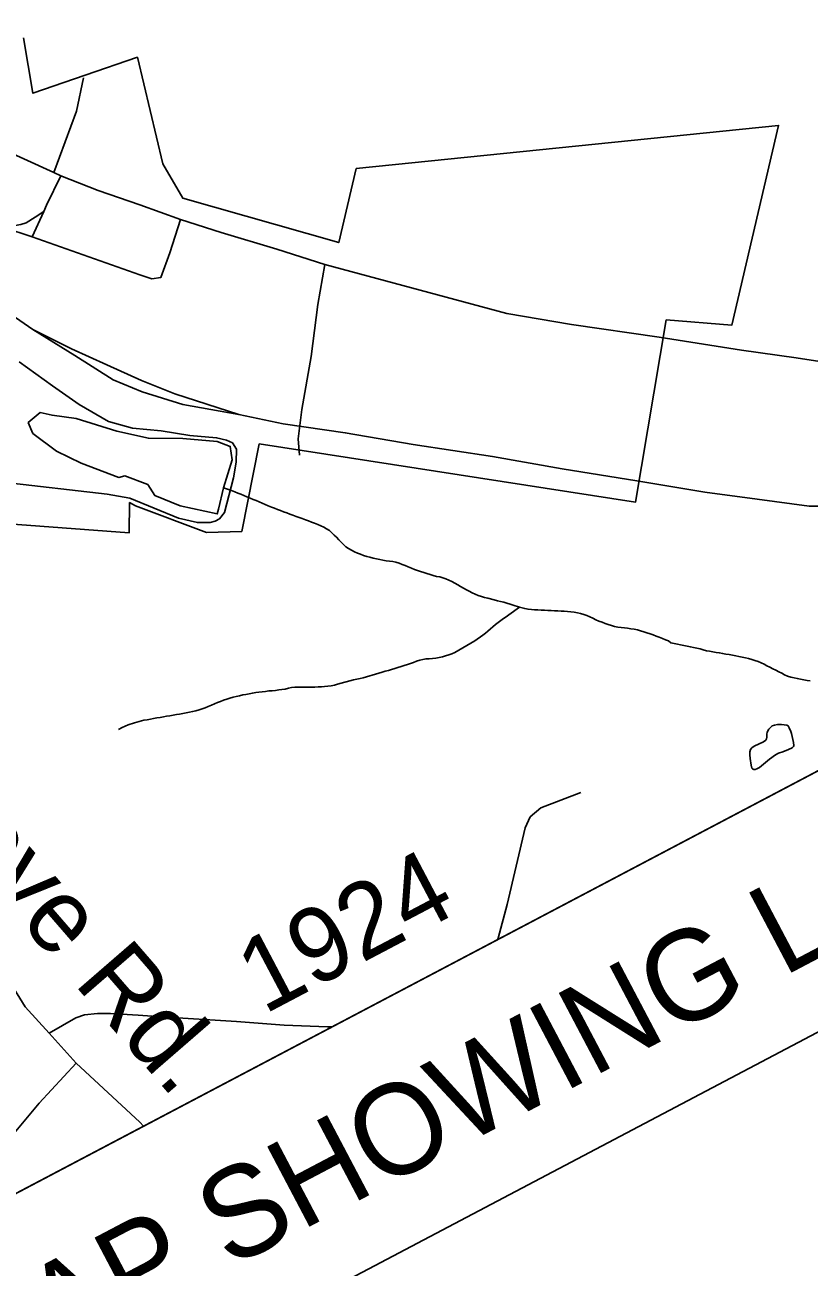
# Model space of a CAD drawing. Extents: x 1379448 to 1382868, y 593769 to 596827.
# Drawn here: x 1379935.9 to 1380091.8, y 595079.7 to 595326.7 of the extents above; entities that cross this region are included whole.
import ezdxf

# ---------------------------------------------------------------- set-up
doc = ezdxf.new("R2010")
doc.units = 0
for name, color, linetype in [('CTL Sheet Text', 7, 'Continuous'), ('Old_Level_1', 7, 'Continuous'), ('Old_Level_11', 7, 'Continuous'), ('Old_Level_29', 7, 'Continuous'), ('Old_Level_32', 7, 'Continuous'), ('Old_Level_35', 7, 'Continuous'), ('Old_Level_44', 7, 'Continuous'), ('Old_Level_48', 7, 'Continuous'), ('Old_Level_49', 7, 'Continuous'), ('Old_Level_62', 7, 'Continuous'), ('Old_Level_8', 7, 'Continuous')]:
    doc.layers.add(name, color=color, linetype=linetype)

msp = doc.modelspace()

# ---------------------------------------------------------------- linework, layer by layer
at = {"layer": 'Old_Level_1'}
msp.add_line((1379782.59, 595014.48), (1380447.79, 595365.17), dxfattribs=at)
msp.add_lwpolyline([(1379782.59, 595014.48), (1380447.79, 595365.17), (1380469.23, 595324.5), (1379804.02, 594973.82)], close=True, dxfattribs=at)
at = {"layer": 'Old_Level_29'}
msp.add_lwpolyline([(1379917.05, 595308.57), (1379941.73, 595297.36), (1379943.11, 595296.68), (1379950.54, 595293.74), (1379958.81, 595290.95), (1379966.9, 595288.02), (1379974.99, 595285.45), (1379986.05, 595282.13), (1379995.58, 595279.03), (1380031.76, 595269.32), (1380044.58, 595267.15), (1380062.05, 595264.62), (1380078.36, 595262.06), (1380089.24, 595260.52), (1380143.01, 595252.19), (1380156.35, 595250.56), (1380166.41, 595248.88), (1380173.7, 595247.81), (1380210.71, 595241.61), (1380212.88, 595241.33)], dxfattribs=at)
at = {"layer": 'Old_Level_32'}
msp.add_line((1379940.77, 595126.25), (1379946.13, 595120.28), dxfattribs=at)
for points in [[(1379834.14, 595274.21), (1379836.12, 595273.42), (1379836.93, 595272.49), (1379837.64, 595271.33), (1379838.6, 595269.4), (1379838.84, 595269.07), (1379841.24, 595264.27), (1379845.01, 595256.93), (1379848.37, 595250.47), (1379852.08, 595243.52), (1379853.91, 595239.94), (1379858.44, 595232.07), (1379873.2, 595210.83), (1379890.84, 595185.94), (1379893.96, 595182.29), (1379900.1, 595176.43), (1379917.01, 595160.6), (1379919.58, 595157.36), (1379926.35, 595146.93), (1379932.52, 595137.16), (1379936.02, 595131.5), (1379940.77, 595126.25)], [(1379997.02, 595127.53), (1379996.12, 595127.5), (1379987.46, 595127.82), (1379977.98, 595128.53), (1379963.11, 595129.47), (1379958.45, 595129.8), (1379952.97, 595130.15), (1379950.35, 595130.17), (1379947.76, 595129.86), (1379946.08, 595129.29), (1379940.77, 595126.25)], [(1379894.35, 595088.2), (1379896.86, 595087.97), (1379904.35, 595089.6), (1379910.09, 595091.85), (1379913.76, 595093.15), (1379917.2, 595094.05), (1379922.27, 595094.82), (1379923.48, 595095.22), (1379924.88, 595095.95), (1379926.29, 595096.87), (1379933.12, 595105.59), (1379938.78, 595112.33), (1379946.13, 595120.28)], [(1379946.13, 595120.28), (1379958.79, 595108.54), (1379959.55, 595107.78)]]:
    msp.add_lwpolyline(points, dxfattribs=at)
at = {"layer": 'Old_Level_35'}
for p, q in [((1379937.42, 595284.53), (1379939.69, 595289.63)), ((1379931.77, 595286.43), (1379937.42, 595284.53))]:
    msp.add_line(p, q, dxfattribs=at)
for points in [[(1379941.73, 595297.36), (1379946.23, 595309.57), (1379947.61, 595316.15)], [(1379939.69, 595289.63), (1379940.24, 595290.87), (1379943.11, 595296.68)], [(1379931.77, 595286.43), (1379935.15, 595287.04), (1379936.17, 595287.37), (1379937.96, 595288.47), (1379939.69, 595289.63)], [(1379937.42, 595284.53), (1379958.82, 595277), (1379961.19, 595276.21), (1379962.94, 595276.46), (1379964.76, 595281.4), (1379966.9, 595288.02)], [(1379990.55, 595241.16), (1379990.27, 595244.42), (1379991.02, 595250.25), (1379992.84, 595260.74), (1379994.19, 595271.08), (1379995.58, 595279.03)], [(1379931.58, 595235.78), (1379952.31, 595233.37), (1379956.82, 595232.58), (1379966.48, 595228.65), (1379970.24, 595227.76), (1379972.75, 595227.76), (1379973.79, 595228.01), (1379974.61, 595228.51), (1379975.6, 595229.73), (1379977.43, 595236.65), (1379977.93, 595239.76), (1379978.01, 595242.34), (1379977.2, 595243.6), (1379976.03, 595244.11), (1379974.06, 595244.62), (1379968.72, 595245.08), (1379963, 595245.97), (1379957.34, 595246.54), (1379952.58, 595247.82), (1379946.75, 595251.26), (1379941.41, 595254.94), (1379934.83, 595259.69)], [(1380029.9, 595144.86), (1380029.99, 595145.1), (1380031.82, 595151.83), (1380035.39, 595167.04), (1380036.35, 595169.23), (1380038.49, 595171.02), (1380046.44, 595174.1)]]:
    msp.add_lwpolyline(points, dxfattribs=at)
at = {"layer": 'Old_Level_44'}
for points in [[(1380192.5, 595230.59), (1380190.44, 595230.58), (1380172.65, 595230.88), (1380154.9, 595230.94), (1380136.64, 595230.75), (1380121.05, 595230.99), (1380104.8, 595231.08), (1380091.84, 595231.04), (1380081.51, 595232.39), (1380071.12, 595233.81), (1380057.56, 595236.06), (1380042.77, 595238.41), (1380028.92, 595240.87), (1380013.14, 595243.25), (1379999.61, 595245.6), (1379987.26, 595247.39), (1379978.45, 595249.24), (1379965.75, 595253.35), (1379959.13, 595256.02), (1379952.22, 595259.1), (1379945.23, 595262.31), (1379937.5, 595266.13), (1379929.48, 595271.61)], [(1380189.94, 595229.24), (1380173.81, 595229.4), (1380151.32, 595229.79), (1380135.18, 595230.15), (1380118.49, 595230.5), (1380106.37, 595230.51), (1380091.84, 595231.04), (1380081.51, 595232.39), (1380071.12, 595233.81), (1380057.56, 595236.06), (1380042.77, 595238.41), (1380028.92, 595240.87), (1380013.14, 595243.25), (1379999.61, 595245.6), (1379987.26, 595247.39), (1379978.45, 595249.24), (1379967.35, 595251.21), (1379959.25, 595253.77), (1379953.5, 595256.15), (1379945.87, 595260.99), (1379937.5, 595266.13), (1379929.48, 595271.61)]]:
    msp.add_lwpolyline(points, dxfattribs=at)
at = {"layer": 'Old_Level_48'}
msp.add_lwpolyline([(1379865.2, 595232.53), (1379956.67, 595225.68), (1379956.75, 595231.73), (1379957.95, 595231.05), (1379972.03, 595225.77), (1379979.06, 595226), (1379982.52, 595243.39), (1380057.3, 595231.78), (1380063.43, 595268.05), (1380076.46, 595266.99), (1380085.77, 595306.72), (1380001.82, 595298.13), (1379998.32, 595283.41), (1379967.33, 595292.28), (1379963.36, 595299.1), (1379958.31, 595320.26), (1379937.54, 595313.11), (1379935.68, 595324.14)], dxfattribs=at)
at = {"layer": 'Old_Level_49'}
msp.add_lwpolyline([(1379865.2, 595232.53), (1379956.67, 595225.68), (1379956.75, 595231.73), (1379957.95, 595231.05), (1379972.03, 595225.77), (1379979.06, 595226), (1379982.52, 595243.39), (1380057.3, 595231.78), (1380063.43, 595268.05), (1380076.46, 595266.99), (1380085.77, 595306.72), (1380001.82, 595298.13), (1379998.32, 595283.41), (1379967.33, 595292.28), (1379963.36, 595299.1), (1379958.31, 595320.26), (1379937.54, 595313.11), (1379935.68, 595324.14)], dxfattribs=at)
at = {"layer": 'Old_Level_62'}
for points in [[(1379975.4, 595234.64), (1379977.14, 595240.22), (1379976.77, 595242.9), (1379974.17, 595243.88), (1379967.32, 595244.46), (1379960.49, 595244.52), (1379954.25, 595245.94), (1379946.12, 595248.46), (1379941.35, 595249.08), (1379938.95, 595249.65), (1379936.61, 595247.64), (1379937.49, 595245.48), (1379942.23, 595241.96), (1379947.14, 595239.58), (1379954.65, 595236.74), (1379955.78, 595237.07), (1379960.38, 595235.3), (1379961.77, 595233.16), (1379966.78, 595231.09), (1379974.17, 595229.49), (1379974.46, 595230.43), (1379975.4, 595234.64)], [(1380034.26, 595210.93), (1380033.02, 595211.35), (1380032.39, 595211.56), (1380031.77, 595211.76), (1380031.14, 595211.94), (1380030.49, 595212.07), (1380029.86, 595212.21), (1380029.22, 595212.37), (1380027.94, 595212.71), (1380027.31, 595212.88), (1380026.68, 595213.07), (1380026.06, 595213.28), (1380025.45, 595213.52), (1380024.85, 595213.79), (1380024.27, 595214.09), (1380023.69, 595214.4), (1380023.12, 595214.72), (1380022.56, 595215.06), (1380021.98, 595215.38), (1380021.41, 595215.71), (1380020.83, 595216.01), (1380020.24, 595216.3), (1380019.63, 595216.55), (1380019.01, 595216.77), (1380018.39, 595216.99), (1380017.75, 595217.06), (1380017.11, 595217.23), (1380016.48, 595217.41), (1380015.85, 595217.61), (1380015.22, 595217.8), (1380014.6, 595218.01), (1380013.98, 595218.22), (1380013.37, 595218.44), (1380012.76, 595218.68), (1380012.15, 595218.95), (1380011.56, 595219.22), (1380010.95, 595219.45), (1380010.32, 595219.67), (1380009.69, 595219.86), (1380009.06, 595220.03), (1380008.41, 595220.11), (1380007.76, 595220.17), (1380007.11, 595220.29), (1380006.47, 595220.42), (1380005.82, 595220.56), (1380005.18, 595220.7), (1380004.54, 595220.86), (1380003.91, 595221.03), (1380003.28, 595221.23), (1380002.67, 595221.45), (1380002.05, 595221.68), (1380001.45, 595221.94), (1380000.87, 595222.25), (1380000.3, 595222.58), (1379999.77, 595222.96), (1379999.28, 595223.4), (1379998.81, 595223.86), (1379998.36, 595224.34), (1379997.91, 595224.82), (1379997.44, 595225.28), (1379996.96, 595225.72), (1379996.46, 595226.15), (1379995.92, 595226.54), (1379995.35, 595226.86), (1379994.74, 595227.12), (1379994.14, 595227.36), (1379993.53, 595227.61), (1379992.92, 595227.84), (1379992.31, 595228.08), (1379991.69, 595228.31), (1379991.08, 595228.54), (1379990.46, 595228.77), (1379989.84, 595228.99), (1379989.23, 595229.22), (1379988.61, 595229.44), (1379987.99, 595229.67), (1379987.38, 595229.9), (1379986.76, 595230.13), (1379986.15, 595230.36), (1379985.54, 595230.6), (1379984.93, 595230.84), (1379984.32, 595231.09), (1379983.71, 595231.34), (1379983.1, 595231.59), (1379982.5, 595231.85), (1379981.9, 595232.11), (1379981.3, 595232.36), (1379980.69, 595232.62), (1379980.08, 595232.87), (1379979.48, 595233.13), (1379978.87, 595233.38), (1379978.26, 595233.63), (1379977.66, 595233.88), (1379977.04, 595234.1), (1379976.42, 595234.31), (1379975.4, 595234.64)], [(1380034.26, 595210.93), (1380032.12, 595209.41), (1380031.58, 595209.03), (1380031.05, 595208.65), (1380030.52, 595208.26), (1380030, 595207.87), (1380029.48, 595207.46), (1380028.98, 595207.04), (1380028.48, 595206.6), (1380027.99, 595206.17), (1380027.49, 595205.74), (1380026.96, 595205.36), (1380025.37, 595204.25), (1380021.39, 595201.95), (1380020.79, 595201.68), (1380020.18, 595201.45), (1380019.55, 595201.24), (1380018.92, 595201.06), (1380018.28, 595200.91), (1380017.63, 595200.8), (1380016.98, 595200.72), (1380016.33, 595200.65), (1380015.7, 595200.69), (1380015.06, 595200.55), (1380014.42, 595200.39), (1380013.78, 595200.22), (1380013.22, 595199.92), (1380012.59, 595199.72), (1380011.97, 595199.53), (1380011.35, 595199.33), (1380010.71, 595199.14), (1380010.09, 595198.94), (1380009.46, 595198.76), (1380008.83, 595198.57), (1380008.2, 595198.37), (1380007.57, 595198.19), (1380006.94, 595198), (1380006.31, 595197.81), (1380003.19, 595196.89), (1380002.56, 595196.74), (1380001.91, 595196.6), (1380001.27, 595196.47), (1379998.09, 595195.65), (1379997.46, 595195.45), (1379996.82, 595195.3), (1379996.18, 595195.21), (1379995.53, 595195.16), (1379994.87, 595195.11), (1379994.21, 595195.08), (1379993.56, 595195.06), (1379991.58, 595195.01), (1379990.93, 595195.01), (1379990.27, 595195.04), (1379989.61, 595195.04), (1379988.97, 595194.97), (1379988.33, 595194.82), (1379987.69, 595194.66), (1379987.04, 595194.56), (1379986.39, 595194.47), (1379985.74, 595194.4), (1379985.08, 595194.33), (1379984.43, 595194.27), (1379983.77, 595194.2), (1379983.12, 595194.12), (1379982.47, 595194.04), (1379981.82, 595193.94), (1379981.18, 595193.84), (1379980.53, 595193.73), (1379979.88, 595193.6), (1379979.24, 595193.48), (1379978.59, 595193.34), (1379977.95, 595193.19), (1379977.32, 595193.03), (1379976.68, 595192.85), (1379976.06, 595192.66), (1379975.44, 595192.44), (1379974.83, 595192.2), (1379974.23, 595191.95), (1379973.62, 595191.69), (1379973.02, 595191.43), (1379972.4, 595191.18), (1379971.8, 595190.94), (1379971.18, 595190.72), (1379970.56, 595190.53), (1379969.92, 595190.35), (1379969.28, 595190.19), (1379968.64, 595190.05), (1379968, 595189.92), (1379967.35, 595189.8), (1379966.7, 595189.68), (1379966.06, 595189.57), (1379965.41, 595189.45), (1379964.76, 595189.34), (1379964.12, 595189.24), (1379963.47, 595189.12), (1379962.82, 595189.01), (1379962.17, 595188.91), (1379961.52, 595188.8), (1379960.88, 595188.68), (1379960.23, 595188.56)], [(1380055.75, 595206.74), (1380055.1, 595206.81), (1380054.44, 595206.89), (1380053.79, 595206.99), (1380053.15, 595207.12), (1380052.52, 595207.3), (1380051.89, 595207.49), (1380051.28, 595207.71), (1380050.66, 595207.94), (1380050.04, 595208.17), (1380049.44, 595208.42), (1380048.85, 595208.72), (1380048.27, 595209.02), (1380047.66, 595209.26), (1380047.04, 595209.49), (1380046.41, 595209.68), (1380045.77, 595209.82), (1380045.12, 595209.94), (1380044.47, 595210.02), (1380043.82, 595210.08), (1380043.16, 595210.12), (1380042.51, 595210.16), (1380041.85, 595210.2), (1380041.19, 595210.23), (1380040.54, 595210.26), (1380039.88, 595210.29), (1380039.23, 595210.32), (1380038.57, 595210.35), (1380037.92, 595210.38), (1380037.26, 595210.42), (1380036.61, 595210.46), (1380035.95, 595210.53), (1380035.3, 595210.64), (1380034.26, 595210.93)], [(1380092.06, 595196.27), (1380091.41, 595196.38), (1380090.76, 595196.5), (1380090.12, 595196.63), (1380089.47, 595196.77), (1380088.83, 595196.9), (1380088.19, 595197.05), (1380087.56, 595197.25), (1380086.96, 595197.51), (1380086.37, 595197.8), (1380085.78, 595198.09), (1380085.2, 595198.38), (1380084.62, 595198.68), (1380084.03, 595198.98), (1380083.44, 595199.28), (1380082.86, 595199.57), (1380082.26, 595199.86), (1380081.67, 595200.13), (1380081.05, 595200.35), (1380080.42, 595200.53), (1380079.78, 595200.7), (1380079.15, 595200.87), (1380078.51, 595201.02), (1380077.87, 595201.15), (1380077.23, 595201.28), (1380076.58, 595201.4), (1380075.93, 595201.51), (1380075.28, 595201.62), (1380074.63, 595201.73), (1380073.99, 595201.83), (1380073.34, 595201.94), (1380072.69, 595202.05), (1380072.05, 595202.16), (1380071.4, 595202.28), (1380070.78, 595202.46), (1380070.15, 595202.64), (1380069.51, 595202.78), (1380068.87, 595202.91), (1380068.22, 595203.04), (1380067.58, 595203.17), (1380066.94, 595203.3), (1380066.29, 595203.43), (1380065.65, 595203.56), (1380065.01, 595203.69), (1380064.37, 595203.82), (1380063.88, 595204.22), (1380063.27, 595204.47), (1380062.67, 595204.71), (1380062.05, 595204.95), (1380061.44, 595205.18), (1380060.82, 595205.42), (1380060.2, 595205.64), (1380059.58, 595205.86), (1380058.95, 595206.06), (1380058.33, 595206.25), (1380057.7, 595206.43), (1380057.05, 595206.56), (1380056.41, 595206.66), (1380055.75, 595206.74)], [(1379960.23, 595188.56), (1379959.59, 595188.44), (1379957.7, 595187.96), (1379956.47, 595187.55), (1379955.88, 595187.28), (1379955.29, 595186.98), (1379954.56, 595186.6)], [(1380088.32, 595185.79), (1380088.71, 595184.06), (1380088.76, 595183.43), (1380088.74, 595183.22), (1380088.47, 595182.98), (1380087.71, 595182.63), (1380086.57, 595182.2), (1380085.75, 595181.9), (1380085.13, 595181.56), (1380083.96, 595180.72), (1380081.93, 595179.06), (1380081.42, 595178.78), (1380081.07, 595178.65), (1380080.81, 595178.66), (1380080.59, 595178.78), (1380080.45, 595178.94), (1380080.31, 595179.53), (1380080.08, 595180.84), (1380080.01, 595181.59), (1380080.04, 595182.17), (1380080.17, 595182.64), (1380080.44, 595182.94), (1380080.88, 595183.27), (1380082.77, 595184.19), (1380083.22, 595184.5), (1380083.37, 595184.74), (1380083.41, 595185.11), (1380083.39, 595185.69), (1380083.49, 595186.08), (1380083.82, 595186.67), (1380084.2, 595187.09), (1380084.51, 595187.32), (1380084.92, 595187.49), (1380085.57, 595187.64), (1380086.31, 595187.63), (1380087.37, 595187.49), (1380087.65, 595187.32), (1380087.88, 595186.96), (1380088.2, 595186.21), (1380088.32, 595185.79)]]:
    msp.add_lwpolyline(points, dxfattribs=at)

# ---------------------------------------------------------------- texts
at = {"layer": 'CTL Sheet Text'}
for s, p in [('    POINT          DESC.           NORTH             EAST          ELEVATION           L STATION       OFFSET', (1379930, 594906.31)), ('1                     B4118-1      596251.6720     1381327.2440           677.16         12+69.03        802.13 LT', (1379949.43, 594869.45)), ('2                     B4118-2      594770.5120     1381808.5600           655.74         10+96.75        740.30 RT', (1379959.15, 594851.03)), ('------------ ---------------- ---------------- ---------------- ---------------- ---------------- ----------------', (1379939.72, 594887.88))]:
    msp.add_text(s, height=10.41667, rotation=27.7977, dxfattribs=at).set_placement(p)
at = {"layer": 'Old_Level_11'}
msp.add_text('Hickory Grove Rd.', height=14.7638, rotation=310.9193, dxfattribs=at).set_placement((1379859.96, 595234.83))
at = {"layer": 'Old_Level_32'}
msp.add_text('VICINITY MAP SHOWING LOCATION OF PROJECT B-4118', height=18, rotation=27.7977, dxfattribs=at).set_placement((1379828.68, 595001.39))
at = {"layer": 'Old_Level_8'}
msp.add_text('1924', height=14.764, rotation=27.7977, dxfattribs=at).set_placement((1379983.45, 595129.86))

doc.saveas('drawing.dxf')
